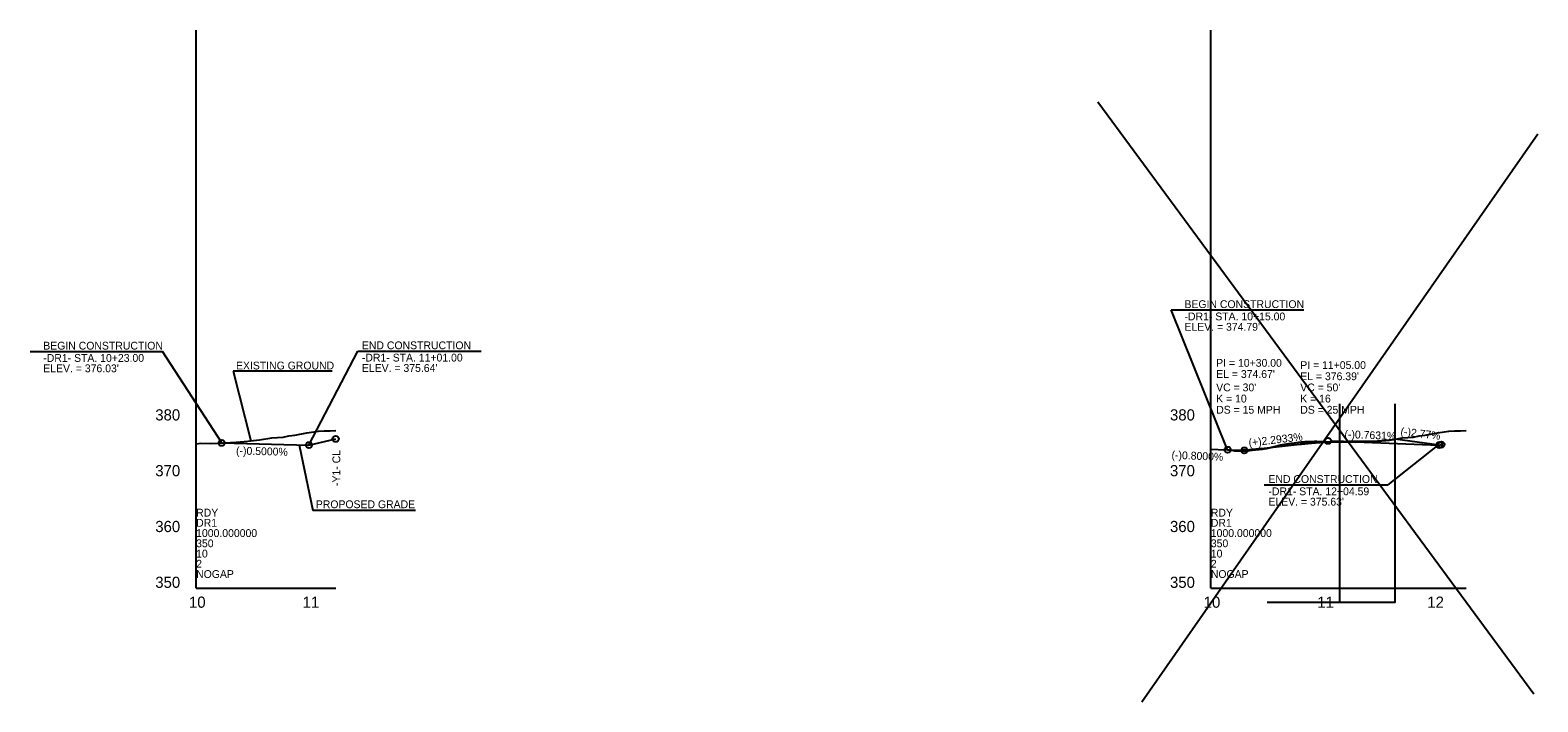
# Model space of a CAD drawing. Extents: x 1625686 to 1640492, y 1161393 to 1175642.
# Drawn here: x 1630056 to 1631406, y 1166802 to 1167403 of the extents above; entities that cross this region are included whole.
import ezdxf

# ---------------------------------------------------------------- set-up
doc = ezdxf.new("R2010")
doc.units = 0
for name, color, linetype in [('Exist Profile Cell', 7, 'Continuous'), ('Exist Vertical Profile Ground Line', 7, 'Continuous'), ('Exist Vertical Profile Horizontal Axis Label Major', 7, 'Continuous'), ('Exist Vertical Profile Vertical Axis Label', 7, 'Continuous'), ('Prop Vertical Profile Curve Label', 7, 'Continuous'), ('Prop Vertical Profile Grade', 7, 'Continuous'), ('Prop Vertical Profile Grade Label', 7, 'Continuous'), ('Prop VPI Label', 7, 'Continuous'), ('Scratch_Level_2', 7, 'Continuous'), ('Scratch_Level_3', 7, 'Continuous'), ('Scratch_Level_5', 7, 'Continuous')]:
    doc.layers.add(name, color=color, linetype=linetype)

msp = doc.modelspace()

# ---------------------------------------------------------------- linework, layer by layer
at = {"layer": 'Exist Profile Cell'}
for p, q in [((1630204.3, 1166903.4), (1630204.3, 1167403.4)), ((1631113.2, 1166903.4), (1631113.2, 1167403.4)), ((1630204.3, 1166903.4), (1630329.3, 1166903.4)), ((1630204.3, 1166903.4), (1630204.3, 1166903.4)), ((1631113.2, 1166903.4), (1631341.8, 1166903.4)), ((1631113.2, 1166903.4), (1631113.2, 1166903.4))]:
    msp.add_line(p, q, dxfattribs=at)
at = {"layer": 'Exist Vertical Profile Ground Line'}
for points in [[(1630204.3, 1167032.9), (1630208.5, 1167033.4), (1630217.5, 1167033.2), (1630224.4, 1167033.5), (1630229.6, 1167033.6), (1630240.1, 1167034.2), (1630240.5, 1167034.2), (1630250.7, 1167035.1), (1630255.8, 1167035.7), (1630261.2, 1167036.2), (1630272, 1167038), (1630282.3, 1167038.7), (1630287.4, 1167039.8), (1630292.8, 1167040.6), (1630303.6, 1167042.7), (1630313.9, 1167044), (1630319.1, 1167044.3), (1630324.5, 1167044.5), (1630329.3, 1167044.8)], [(1631259.1, 1167035.1), (1631259.8, 1167035.1), (1631260.4, 1167035.1), (1631261, 1167035.1), (1631261.9, 1167035.2), (1631262.3, 1167035.2), (1631262.9, 1167035.3), (1631263.5, 1167035.3), (1631264.2, 1167035.4), (1631264.8, 1167035.4), (1631265.4, 1167035.5), (1631266, 1167035.5), (1631266.7, 1167035.6), (1631267.3, 1167035.6), (1631267.9, 1167035.7), (1631268.6, 1167035.7), (1631269.2, 1167035.8), (1631269.8, 1167035.8), (1631270.4, 1167035.9), (1631271.1, 1167035.9), (1631271.7, 1167036), (1631272.3, 1167036.1), (1631273, 1167036.1), (1631273.6, 1167036.2), (1631274.2, 1167036.3), (1631274.8, 1167036.4), (1631275.5, 1167036.5), (1631276.1, 1167036.6), (1631276.7, 1167036.7), (1631277.4, 1167036.8), (1631278, 1167036.9), (1631278.6, 1167037), (1631284.5, 1167038), (1631294.8, 1167038.7), (1631299.9, 1167039.8), (1631305.3, 1167040.6), (1631316.1, 1167042.7), (1631326.4, 1167044), (1631331.6, 1167044.3), (1631336.9, 1167044.5), (1631341.8, 1167044.8)], [(1631113.2, 1167028.1), (1631119.8, 1167027.6), (1631128.2, 1167027.3), (1631132.1, 1167027.1), (1631134.5, 1167026.6), (1631137.9, 1167026.6), (1631138.5, 1167026.6), (1631139.1, 1167026.6), (1631139.8, 1167026.6), (1631140.7, 1167026.7), (1631141, 1167026.6), (1631141.6, 1167026.6), (1631142.3, 1167026.6), (1631142.9, 1167026.6), (1631143.5, 1167026.6), (1631144.2, 1167026.5), (1631144.8, 1167026.5), (1631145.4, 1167026.5), (1631145.7, 1167026.5), (1631146, 1167026.6), (1631146.7, 1167026.7), (1631147.3, 1167026.8), (1631147.9, 1167026.9), (1631148.6, 1167027.1), (1631149.2, 1167027.2), (1631149.8, 1167027.2), (1631150.4, 1167027.3), (1631151.1, 1167027.3), (1631151.7, 1167027.4), (1631152.3, 1167027.5), (1631153, 1167027.5), (1631153.6, 1167027.6), (1631154.2, 1167027.6), (1631154.8, 1167027.7), (1631155.5, 1167027.8), (1631156.1, 1167027.8), (1631156.7, 1167027.9), (1631157.4, 1167027.9), (1631158, 1167028), (1631158.6, 1167028), (1631159.2, 1167028.1), (1631159.9, 1167028.2), (1631160.5, 1167028.3), (1631161.1, 1167028.4), (1631161.8, 1167028.5), (1631162.4, 1167028.6), (1631163.1, 1167028.7), (1631163.6, 1167028.9), (1631164.3, 1167029), (1631164.9, 1167029.2), (1631165.5, 1167029.3), (1631166.2, 1167029.5), (1631166.8, 1167029.6), (1631167.4, 1167029.8), (1631168, 1167029.9), (1631168.7, 1167030.1), (1631169.3, 1167030.2), (1631169.9, 1167030.3), (1631170.6, 1167030.5), (1631171.2, 1167030.6), (1631171.5, 1167030.7), (1631171.8, 1167030.8), (1631172.5, 1167031), (1631173.1, 1167031.2), (1631173.7, 1167031.4), (1631174.3, 1167031.5), (1631175, 1167031.7), (1631175.6, 1167031.8), (1631176.2, 1167031.9), (1631176.9, 1167032), (1631177.5, 1167032.1), (1631178.1, 1167032.2), (1631178.9, 1167032.3), (1631179.4, 1167032.4), (1631180, 1167032.5), (1631180.6, 1167032.6), (1631181.3, 1167032.7), (1631181.9, 1167032.8), (1631182.5, 1167032.9), (1631183.1, 1167033), (1631183.8, 1167033.1), (1631184.4, 1167033.1), (1631185.2, 1167033.3), (1631185.7, 1167033.3), (1631186.3, 1167033.4), (1631186.9, 1167033.4), (1631187.5, 1167033.5), (1631188.2, 1167033.6), (1631188.8, 1167033.7), (1631189.4, 1167033.7), (1631190.1, 1167033.8), (1631190.7, 1167033.9), (1631191.3, 1167034), (1631191.9, 1167034.1), (1631192.6, 1167034.2), (1631193.2, 1167034.2), (1631193.8, 1167034.3), (1631194.5, 1167034.4), (1631195.3, 1167034.5), (1631195.7, 1167034.6), (1631196.3, 1167034.6)], [(1631196.3, 1167034.6), (1631197, 1167034.6), (1631197.6, 1167034.7), (1631198.2, 1167034.7), (1631198.9, 1167034.7), (1631199.5, 1167034.8), (1631200.1, 1167034.8), (1631200.7, 1167034.8), (1631201.4, 1167034.8), (1631202, 1167034.8), (1631202.6, 1167034.8), (1631203.3, 1167034.9), (1631203.9, 1167034.9), (1631204.5, 1167034.9), (1631205.4, 1167034.9), (1631205.8, 1167034.9), (1631206.4, 1167035), (1631207, 1167035), (1631207.7, 1167035), (1631208.3, 1167034.9), (1631208.9, 1167034.9), (1631209.5, 1167034.8), (1631210.2, 1167034.8), (1631210.8, 1167034.8), (1631211.4, 1167034.7), (1631212.1, 1167034.7), (1631212.7, 1167034.7), (1631213.3, 1167034.6), (1631213.9, 1167034.6), (1631214.6, 1167034.6), (1631215.5, 1167034.5), (1631215.8, 1167034.5), (1631216.5, 1167034.5), (1631217.1, 1167034.5), (1631217.7, 1167034.5), (1631218.3, 1167034.5), (1631219, 1167034.5), (1631219.6, 1167034.5), (1631220.2, 1167034.5), (1631220.8, 1167034.5), (1631221.5, 1167034.5), (1631222.1, 1167034.6), (1631222.7, 1167034.6), (1631223.4, 1167034.6), (1631224, 1167034.6), (1631224.6, 1167034.6), (1631225.2, 1167034.6), (1631225.9, 1167034.6), (1631226.5, 1167034.6), (1631227.1, 1167034.6), (1631227.7, 1167034.7), (1631228.4, 1167034.7), (1631229, 1167034.7), (1631229.6, 1167034.7), (1631230.3, 1167034.7), (1631230.9, 1167034.7), (1631231.5, 1167034.8), (1631232.1, 1167034.8), (1631232.8, 1167034.8), (1631233.4, 1167034.8), (1631234, 1167034.9), (1631234.7, 1167034.9), (1631235.3, 1167034.9), (1631235.9, 1167034.9), (1631236.5, 1167035), (1631237.2, 1167035), (1631237.8, 1167035), (1631238.4, 1167035.1), (1631239, 1167035.1), (1631239.7, 1167035.1), (1631240.3, 1167035.2), (1631240.9, 1167035.1), (1631241.6, 1167035.1), (1631242.2, 1167035.1), (1631242.8, 1167035.1), (1631243.4, 1167035.1), (1631244.1, 1167035.1), (1631244.7, 1167035.1), (1631245.3, 1167035.1), (1631246, 1167035.1), (1631246.6, 1167035.1), (1631247.5, 1167035.1), (1631247.8, 1167035.1), (1631248.5, 1167035.1), (1631249.1, 1167035.1), (1631249.7, 1167035.1), (1631250.4, 1167035.1), (1631251, 1167035.1), (1631251.6, 1167035.1), (1631252.2, 1167035.1), (1631252.9, 1167035.1), (1631253.5, 1167035.1), (1631254.1, 1167035.1), (1631254.7, 1167035.1), (1631255.4, 1167035.1), (1631256, 1167035.1), (1631256.6, 1167035.1), (1631257.3, 1167035.1), (1631257.9, 1167035.1), (1631258.5, 1167035.1), (1631259.1, 1167035.1)]]:
    msp.add_lwpolyline(points, dxfattribs=at)
at = {"layer": 'Prop Vertical Profile Grade'}
for p, q in [((1631128.2, 1167027.4), (1631128.2, 1167027.4)), ((1631158.2, 1167028.5), (1631193.2, 1167032.5)), ((1631243.2, 1167034.4), (1631317.8, 1167031.6)), ((1631317.8, 1167031.6), (1631319.8, 1167032.1))]:
    msp.add_line(p, q, dxfattribs=at)
msp.add_lwpolyline([(1630227.3, 1167033.6), (1630305.3, 1167031.6), (1630329.3, 1167037.2)], dxfattribs=at)
for points in [[(1631128.2, 1167027.4), (1631128.8, 1167027.3), (1631129.4, 1167027.3), (1631130, 1167027.3), (1631130.6, 1167027.3), (1631131.2, 1167027.3), (1631131.8, 1167027.2), (1631132.4, 1167027.2), (1631133, 1167027.2), (1631133.6, 1167027.2), (1631134.2, 1167027.2), (1631134.8, 1167027.2), (1631135.4, 1167027.2), (1631136, 1167027.2), (1631136.6, 1167027.2), (1631137.2, 1167027.2), (1631137.8, 1167027.2), (1631138.4, 1167027.2), (1631139, 1167027.2), (1631139.6, 1167027.2), (1631140.2, 1167027.2), (1631140.8, 1167027.3), (1631141.4, 1167027.3), (1631142, 1167027.3), (1631142.6, 1167027.3), (1631143.2, 1167027.3), (1631143.8, 1167027.4), (1631144.4, 1167027.4), (1631145, 1167027.4), (1631145.6, 1167027.4), (1631146.2, 1167027.5), (1631146.8, 1167027.5), (1631147.4, 1167027.5), (1631148, 1167027.6), (1631148.6, 1167027.6), (1631149.2, 1167027.6), (1631149.8, 1167027.7), (1631150.4, 1167027.7), (1631151, 1167027.8), (1631151.6, 1167027.8), (1631152.2, 1167027.9), (1631152.8, 1167027.9), (1631153.4, 1167028), (1631154, 1167028), (1631154.6, 1167028.1), (1631155.2, 1167028.1), (1631155.8, 1167028.2), (1631156.4, 1167028.3), (1631157, 1167028.3), (1631157.6, 1167028.4), (1631158.2, 1167028.5)], [(1631193.2, 1167032.5), (1631194.2, 1167032.6), (1631195.2, 1167032.7), (1631196.2, 1167032.8), (1631197.2, 1167032.9), (1631198.2, 1167033), (1631199.2, 1167033.1), (1631200.2, 1167033.2), (1631201.2, 1167033.3), (1631202.2, 1167033.4), (1631203.2, 1167033.5), (1631204.2, 1167033.6), (1631205.2, 1167033.6), (1631206.2, 1167033.7), (1631207.2, 1167033.8), (1631208.2, 1167033.9), (1631209.2, 1167033.9), (1631210.2, 1167034), (1631211.2, 1167034.1), (1631212.2, 1167034.1), (1631213.2, 1167034.2), (1631214.2, 1167034.2), (1631215.2, 1167034.3), (1631216.2, 1167034.3), (1631217.2, 1167034.4), (1631218.2, 1167034.4), (1631219.2, 1167034.4), (1631220.2, 1167034.5), (1631221.2, 1167034.5), (1631222.2, 1167034.5), (1631223.2, 1167034.5), (1631224.2, 1167034.6), (1631225.2, 1167034.6), (1631226.2, 1167034.6), (1631227.2, 1167034.6), (1631228.2, 1167034.6), (1631229.2, 1167034.6), (1631230.2, 1167034.6), (1631231.2, 1167034.6), (1631232.2, 1167034.6), (1631233.2, 1167034.6), (1631234.2, 1167034.6), (1631235.2, 1167034.6), (1631236.2, 1167034.6), (1631237.2, 1167034.6), (1631238.2, 1167034.5), (1631239.2, 1167034.5), (1631240.2, 1167034.5), (1631241.2, 1167034.5), (1631242.2, 1167034.4), (1631243.2, 1167034.4)]]:
    msp.add_spline(points, degree=3, dxfattribs=at)
at = {"layer": 'Prop Vertical Profile Grade Label'}
for p, q in [((1631128.2, 1167027.4), (1631077.8, 1167152.7)), ((1631077.8, 1167152.7), (1631196.5, 1167152.7)), ((1630055.6, 1167115.5), (1630174.3, 1167115.5)), ((1630227.3, 1167033.6), (1630174.3, 1167115.5)), ((1630305.3, 1167031.6), (1630349, 1167115.8)), ((1630349, 1167115.8), (1630459.7, 1167115.8)), ((1630296.5, 1167031.8), (1630308.8, 1166972.9)), ((1631317.8, 1167032.5), (1631271.7, 1166996)), ((1631161, 1166996), (1631271.7, 1166996)), ((1630400.7, 1166972.9), (1630308.8, 1166972.9))]:
    msp.add_line(p, q, dxfattribs=at)
at = {"layer": 'Prop VPI Label'}
for p, q in [((1630326.1, 1167098), (1630237.5, 1167098)), ((1630237.5, 1167098), (1630253.2, 1167035.4)), ((1631128.2, 1167027.4), (1631140.4, 1167026.9)), ((1631158.2, 1167028.5), (1631145.9, 1167027.1)), ((1631193.2, 1167032.5), (1631215.4, 1167035)), ((1631243.2, 1167034.4), (1631220.9, 1167035.2))]:
    msp.add_line(p, q, dxfattribs=at)
for centre in [(1630227.3, 1167033.6), (1630329.3, 1167037.2), (1631218.2, 1167035.4), (1630305.3, 1167031.6), (1631128.2, 1167027.4), (1631143.2, 1167026.8), (1631317.8, 1167031.6), (1631319.8, 1167032.1)]:
    msp.add_circle(centre, 2.75, dxfattribs=at)
at = {"layer": 'Scratch_Level_2'}
msp.add_line((1631317.8, 1167031.6), (1631278.2, 1167036.9), dxfattribs=at)
at = {"layer": 'Scratch_Level_3'}
for p, q in [((1631012.1, 1167339.1), (1631402.5, 1166808.7)), ((1631051.5, 1166801.6), (1631406.1, 1167310.5))]:
    msp.add_line(p, q, dxfattribs=at)
at = {"layer": 'Scratch_Level_5'}
for points in [[(1631163.7, 1166890.9), (1631228.7, 1166890.9), (1631228.7, 1167068.5)], [(1631213.2, 1166890.9), (1631278.2, 1166890.9), (1631278.2, 1167068.5)]]:
    msp.add_lwpolyline(points, dxfattribs=at)

# ---------------------------------------------------------------- texts
at = {"layer": 'Exist Profile Cell'}
for s, p in [('RDY', (1630204.3, 1166967.6)), ('RDY', (1631113.2, 1166967.6)), ('1000.000000', (1630204.3, 1166949.3)), ('DR1', (1630204.3, 1166958.5)), ('DR1', (1631113.2, 1166958.5)), ('1000.000000', (1631113.2, 1166949.3)), ('350', (1630204.3, 1166940.1)), ('350', (1631113.2, 1166940.1)), ('2', (1630204.3, 1166921.8)), ('10', (1630204.3, 1166930.9)), ('2', (1631113.2, 1166921.8)), ('10', (1631113.2, 1166930.9)), ('NOGAP', (1630204.3, 1166912.6)), ('NOGAP', (1631113.2, 1166912.6))]:
    msp.add_text(s, height=7, dxfattribs=at).set_placement(p)
at = {"layer": 'Exist Vertical Profile Horizontal Axis Label Major'}
for s, p in [('10', (1630197.9, 1166885.9)), ('11', (1630299.7, 1166885.9)), ('10', (1631106.8, 1166885.9)), ('11', (1631208.6, 1166885.9)), ('12', (1631307.1, 1166885.9))]:
    msp.add_text(s, height=10, dxfattribs=at).set_placement(p)
at = {"layer": 'Exist Vertical Profile Vertical Axis Label'}
for s, p in [('380', (1630167.7, 1167053.7)), ('380', (1631076.6, 1167053.7)), ('370', (1630167.7, 1167003.7)), ('370', (1631076.6, 1167003.7)), ('360', (1630167.7, 1166953.7)), ('360', (1631076.6, 1166953.7)), ('350', (1630167.7, 1166903.7)), ('350', (1631076.6, 1166903.7))]:
    msp.add_text(s, height=10, dxfattribs=at).set_placement(p)
at = {"layer": 'Prop Vertical Profile Curve Label'}
for s, p in [("VC = 30'", (1631118, 1167079.8)), ('K = 10', (1631118, 1167069.8)), ("VC = 50'", (1631193.3, 1167079.8)), ('K = 16', (1631193.3, 1167069.8)), ('DS = 15 MPH', (1631118, 1167059.8)), ('DS = 25 MPH', (1631193.3, 1167059.8))]:
    msp.add_text(s, height=7, dxfattribs=at).set_placement(p)
at = {"layer": 'Prop Vertical Profile Grade Label'}
for s, rotation, p in [('(+)2.2933%', 6.5507, (1631147.4, 1167030.3)), ('(-)0.7631%', 357.8149, (1631232.8, 1167038)), ('(-)0.5000%', 358.5679, (1630240, 1167023.2)), ('(-)0.8000%', 357.7094, (1631077.9, 1167019.4))]:
    msp.add_text(s, height=7, rotation=rotation, dxfattribs=at).set_placement(p)
msp.add_text('PROPOSED GRADE', height=7, dxfattribs=at).set_placement((1630311.5, 1166975.1))
at = {"layer": 'Prop VPI Label'}
for s, p in [('BEGIN CONSTRUCTION', (1631089.6, 1167154.4)), ('-DR1- STA. 10+15.00', (1631089.6, 1167143.4)), ("ELEV. = 374.79'", (1631089.6, 1167134.1)), ('BEGIN CONSTRUCTION', (1630067.4, 1167117.2)), ('END CONSTRUCTION', (1630352.8, 1167117.5)), ('-DR1- STA. 10+23.00', (1630067.4, 1167106.2)), ("ELEV. = 376.03'", (1630067.4, 1167096.9)), ('EXISTING GROUND', (1630240, 1167099.4)), ('-DR1- STA. 11+01.00', (1630352.8, 1167106.5)), ("ELEV. = 375.64'", (1630352.8, 1167097.2)), ('PI = 10+30.00', (1631118, 1167101.8)), ('PI = 11+05.00', (1631193.3, 1167099.8)), ("EL = 374.67'", (1631118, 1167091.8)), ("EL = 376.39'", (1631193.3, 1167089.8)), ('END CONSTRUCTION', (1631164.8, 1166997.7)), ('-DR1- STA. 12+04.59', (1631164.8, 1166986.7)), ("ELEV. = 375.63'", (1631164.8, 1166977.4))]:
    msp.add_text(s, height=7, dxfattribs=at).set_placement(p)
msp.add_text('-Y1- CL', height=7, rotation=90, dxfattribs=at).set_placement((1630333.4, 1166995))
at = {"layer": 'Scratch_Level_2'}
msp.add_text('(-)2.77%', height=7, rotation=353.2284, dxfattribs=at).set_placement((1631282.8, 1167040.6))

doc.saveas('drawing.dxf')
